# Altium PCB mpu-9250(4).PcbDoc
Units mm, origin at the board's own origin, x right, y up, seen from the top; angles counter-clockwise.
Board outline 66.04 x 76.71 mm, 2 copper layers (Top Layer, Bottom Layer); 14 components, 28 nets, 182 pads, 22 vias.
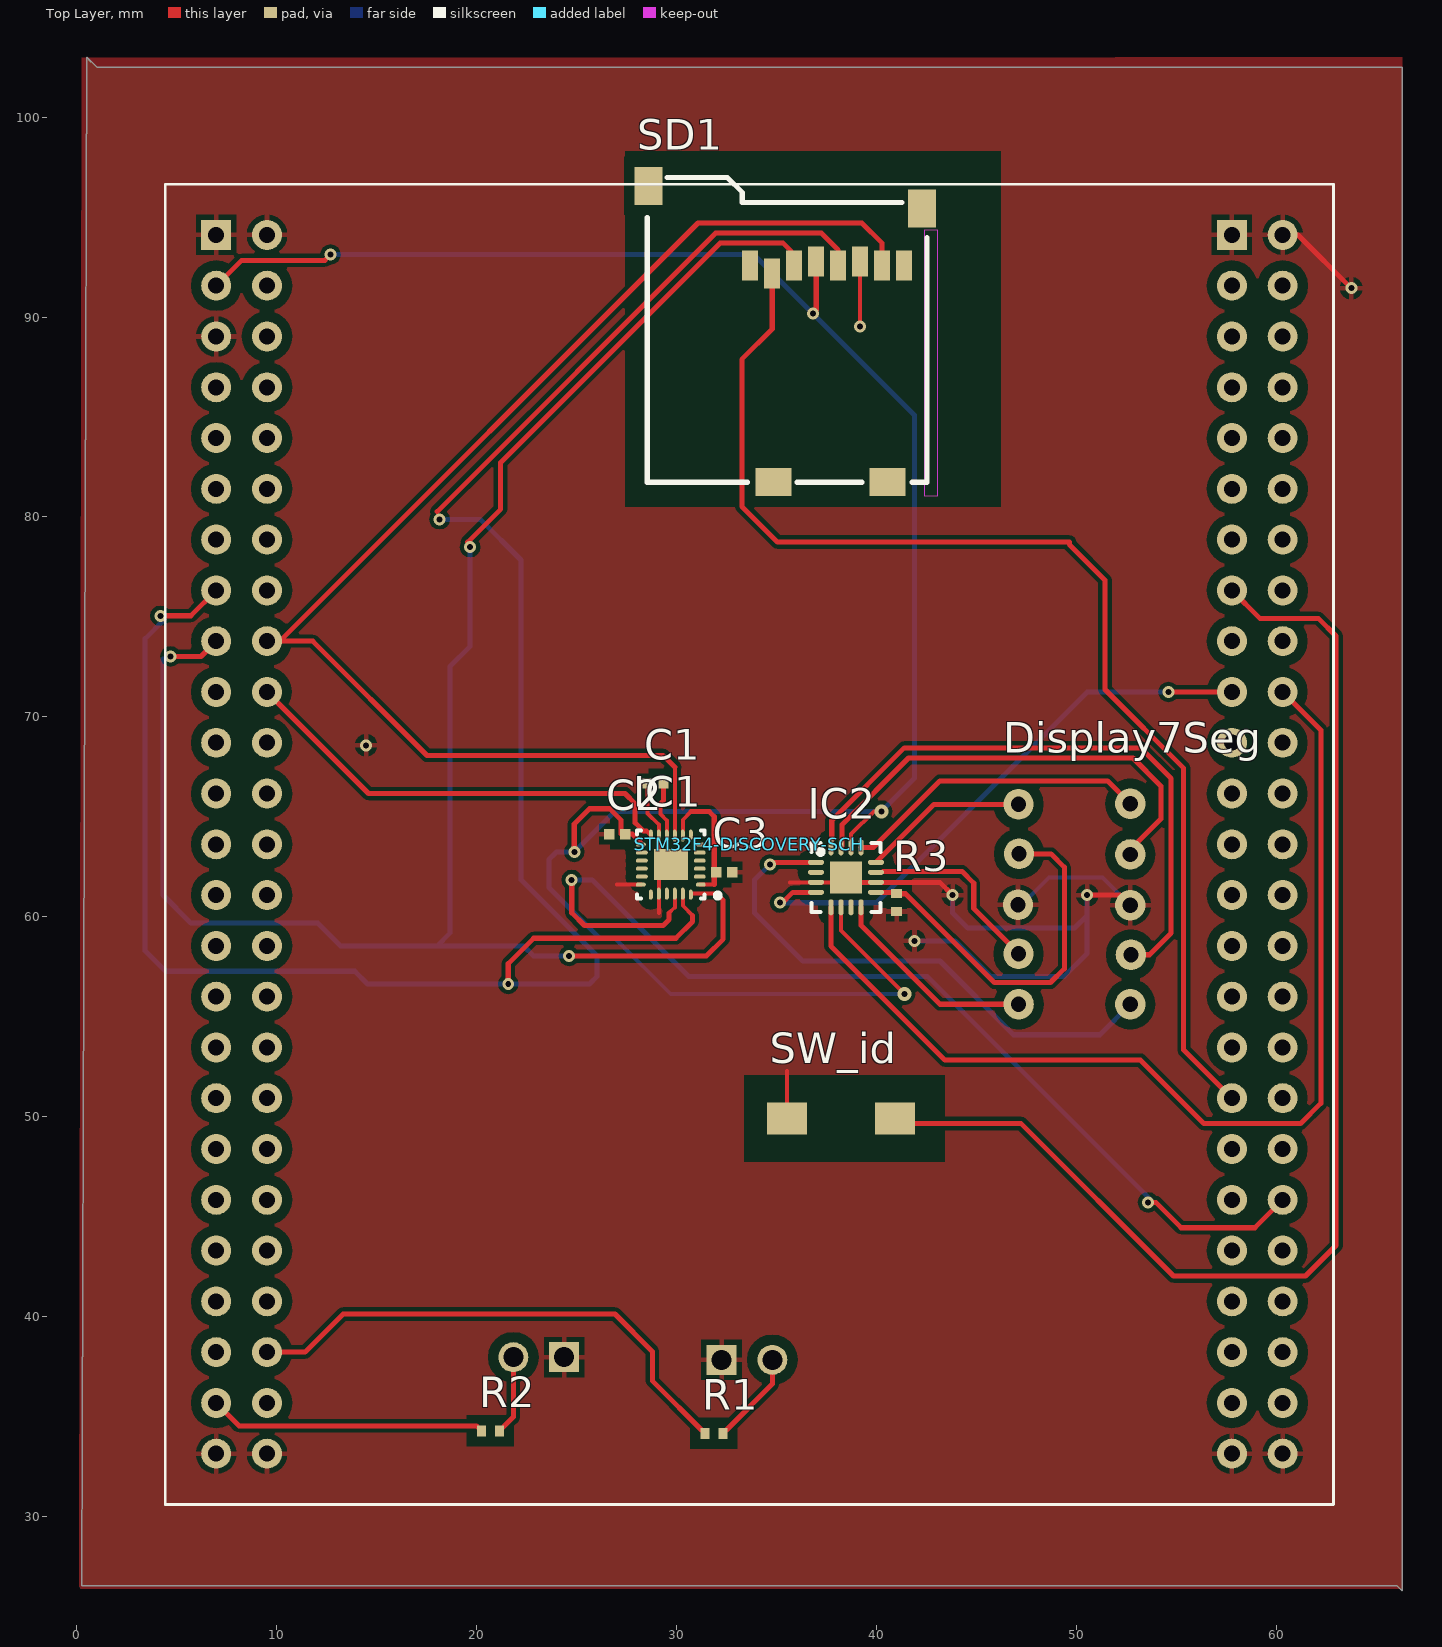
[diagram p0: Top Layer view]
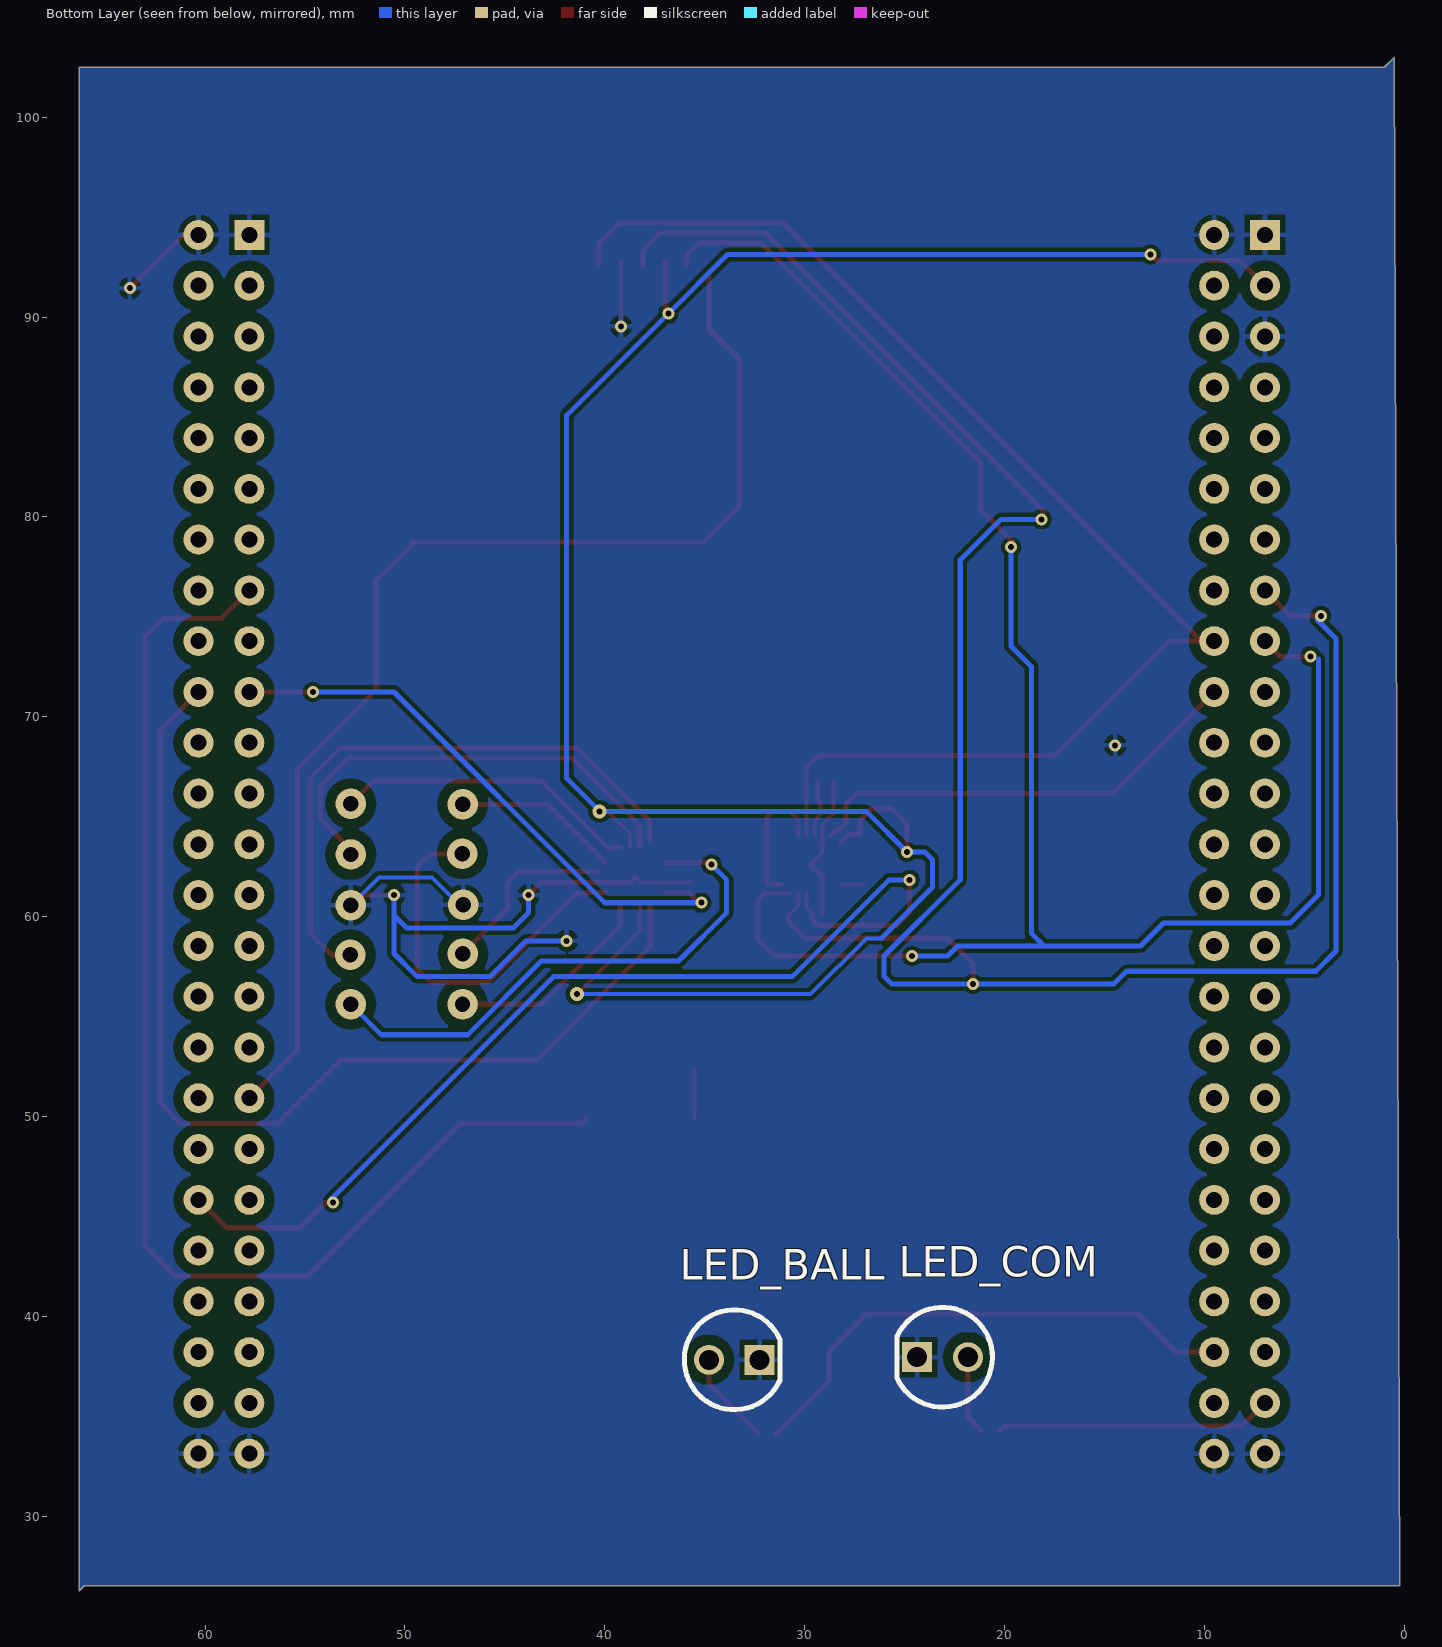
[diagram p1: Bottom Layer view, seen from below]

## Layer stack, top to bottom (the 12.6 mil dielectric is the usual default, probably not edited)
Top Solder: solder mask 0.0102, Solder Resist, Dk 3.5
Top Layer: signal copper 0.0356
Dielectric 1: dielectric 0.32, FR-4, Dk 4.8
Bottom Layer: signal copper 0.0356
Bottom Solder: solder mask 0.0102, Solder Resist, Dk 3.5

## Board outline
0.508,102.997 1.016,102.489 66.294,102.489 66.294,26.289 66.04,26.543 0.254,26.543

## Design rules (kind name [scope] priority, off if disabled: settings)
Clearance [All] p1: gap=0.2 ignorepadtopadclearanceinfootprint=FALSE except(0.5: SMDPad-Poly THPad-Poly)
PolygonConnect [All] p1: connectstyle=Relief reliefconductorwidth=0.254 reliefentries=4 polygonreliefangle="90 Angle" airgapwidth=0.254
RoutingVias [All] p1: holewidth=0.3 width=0.7 viastyle="Through Hole" minholewidth=0.3 minwidth=0.7 maxholewidth=3 maxwidth=3
SolderMaskExpansion [All] p1: expansion=0.102
Width [All] p1: maxlimit=2 minlimit=0.2 preferedwidth=0.3
30 further rules are at their usual default settings.

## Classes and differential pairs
component class mpu-9250: C1 C2 C3 Display7Seg IC1 IC2 LED_BALL LED_COM R1 R2 R3 SD1 SW_id

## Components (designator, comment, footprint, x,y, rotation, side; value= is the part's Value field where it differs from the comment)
C1 "100nF" 0402-CAP 28.956,66.675 r180 top value=100n
C2 "100nF" 0402-CAP 27.051,64.135 r180 top value=100n
C3 "1uF" 0402-CAP 32.385,62.23 r0 top value=1u
Display7Seg "HDSP-F513" "New footprint 1"#1 49.911,60.452 r180 top
IC1 "MPU-9250" MPU-9250 29.718,62.611 r180 top
IC2 "STMPE811QTR" QFN16_N 38.481,61.976 r0 top
LED_BALL "LED" LED-5MM-PCB 33.528,37.846 r180 bottom
LED_COM "LED" LED-5MM-PCB 23.114,37.973 r0 bottom
R1 "330R" 0402-RES-HD 31.877,34.163 r0 top value=330
R2 "330R" 0402-RES-HD 20.701,34.29 r0 top value=330
R3 "10K" 0402-RES-HD 41.021,60.706 r270 top
SD1 "2908-05WB-MG" "New footprint 1"#2 35.433,89.154 r0 top
STM32F4-DISCOVERY-SCH "STM32F4-DISCOVERY-SCH" STM32F4-DISCOVERY-PCB 33.655,63.627 r0 top
SW_id "SWITCH TACTILE 6 x 3.5 x 4.3 mm" PCBComponent 38.227,49.911 r180 top

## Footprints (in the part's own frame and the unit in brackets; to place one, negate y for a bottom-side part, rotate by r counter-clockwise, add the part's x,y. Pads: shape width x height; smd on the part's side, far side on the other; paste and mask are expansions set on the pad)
0402-CAP [mm] "Chip Capacitor, Body 1.0x0.5mm, Height 0.6mm, IPC Medium Density"
  rect 0.52x0.52 smd: 1(-0.4,0) 2(0.4,0)
  body extent -0.55,-0.3 0.55,0.3, height 0.33
0402-RES-HD [mm] "Chip Resistor, Body 1.0x0.5mm, IPC High Density"
  rect 0.45x0.55 smd: 1(-0.45,0) 2(0.45,0)
  body extent -0.52,-0.27 0.53,0.28, height 0.4
LED-5MM-PCB [mm]
  rect 1.5x1.5 hole 1: 1(1.27,0)
  round 1.5 hole 1: 2(-1.27,0)
  silkscreen extent -2.5,-2.5 2.28,2.5, body extent -2.98,-3.01 2.44,3.01, height 8.59
MPU-9250 [mm] "IMU ACCEL/GYRO/MAG I2C/SPI 24QFN"
  oval 0.5x0.2 smd: 1(-1.5,1) 6(-1.5,-1) 13(1.5,-1) 18(1.5,1)
  oval 0.6x0.2 smd: 2(-1.45,0.6) 3(-1.45,0.2) 4(-1.45,-0.2) 5(-1.45,-0.6) 14(1.45,-0.6) 15(1.45,-0.2) 16(1.45,0.2) 17(1.45,0.6)
  oval 0.2x0.5 smd: 7(-1,-1.5) 12(1,-1.5) 19(1,1.5) 24(-1,1.5)
  oval 0.2x0.6 smd: 8(-0.6,-1.45) 9(-0.2,-1.45) 10(0.2,-1.45) 11(0.6,-1.45) 20(0.6,1.45) 21(0.2,1.45) 22(-0.2,1.45) 23(-0.6,1.45)
  rect 1.7x1.54 smd: 25(0,0)
  silkscreen extent -2.48,-1.7 1.7,1.7, body extent -1.55,-1.55 1.55,1.55, height 1.05
"New footprint 1"#1 [mil]
  round 60 hole 30: 1(-110,190) 2(-111.22,92.52) 3(-110,-5) 4(-110,-105) 5(-110,-205) 6(110,190) 7(110.24,90.55) 8(111.22,-5.91) 9(109.25,-106.3) 10(110.24,-203.74)
  body extent -149,-255 150,245, height 283
"New footprint 1"#2 [mil]
  rect 31.5x59.06 smd: 1(-68.5,135.04) 2(-25.2,119.29) 3(18.11,135.04) 4(61.42,142.91) 5(104.72,135.04) 6(148.03,142.91) 7(191.34,135.04) 8(234.65,135.04)
  rect 55.12x74.8 smd: M1(269.29,246.85) M2(-269.29,291.73)
  rect 70.87x55.12 smd: M3(201.97,-291.73) M4(-22.44,-291.73)
  silkscreen extent -271,-292 280,308, body extent -269,-292 282,309, height 75
PCBComponent [mm]
  rect 2x1.6 smd: 1(-2.7,0) 2(2.7,0)
  body extent -3.65,-1.75 3.65,1.75, height 5
QFN16_N [mm] "QFN, 16-Leads, Body 3x3mm, Pitch 0.5mm, Thermal Pad 1.6x1.6mm, IPC Medium Density"
  oval 0.8x0.25 smd: 1(-1.5,0.75) 2(-1.5,0.25) 3(-1.5,-0.25) 4(-1.5,-0.75) 9(1.5,-0.75) 10(1.5,-0.25) 11(1.5,0.25) 12(1.5,0.75)
  oval 0.25x0.8 smd: 5(-0.75,-1.5) 6(-0.25,-1.5) 7(0.25,-1.5) 8(0.75,-1.5) 13(0.75,1.5) 14(0.25,1.5) 15(-0.25,1.5) 16(-0.75,1.5)
  rect 1.6x1.6 smd: TH(0,0)
  silkscreen extent -1.73,-1.73 1.73,1.73, body extent -1.58,-1.58 1.58,1.58, height 1
STM32F4-DISCOVERY-PCB [mm]
  rect 1.5x1.5 hole 0.8: P1_1(-26.67,30.48) P2_1(24.13,30.48)
  round 1.5 hole 0.8: P1_2(-24.13,30.48) P1_3(-26.67,27.94) P1_4(-24.13,27.94) P1_5(-26.67,25.4) P1_6(-24.13,25.4) P1_7(-26.67,22.86) P1_8(-24.13,22.86) P1_9(-26.67,20.32) P1_10(-24.13,20.32) P1_11(-26.67,17.78) P1_12(-24.13,17.78) P1_13(-26.67,15.24) P1_14(-24.13,15.24) P1_15(-26.67,12.7) P1_16(-24.13,12.7) P1_17(-26.67,10.16) P1_18(-24.13,10.16) P1_19(-26.67,7.62) P1_20(-24.13,7.62) P1_21(-26.67,5.08) P1_22(-24.13,5.08) P1_23(-26.67,2.54) P1_24(-24.13,2.54) P1_25(-26.67,0) P1_26(-24.13,0) P1_27(-26.67,-2.54) P1_28(-24.13,-2.54) P1_29(-26.67,-5.08) P1_30(-24.13,-5.08) P1_31(-26.67,-7.62) P1_32(-24.13,-7.62) P1_33(-26.67,-10.16) P1_34(-24.13,-10.16) P1_35(-26.67,-12.7) P1_36(-24.13,-12.7) P1_37(-26.67,-15.24) P1_38(-24.13,-15.24) P1_39(-26.67,-17.78) P1_40(-24.13,-17.78) P1_41(-26.67,-20.32) P1_42(-24.13,-20.32) P1_43(-26.67,-22.86) P1_44(-24.13,-22.86) P1_45(-26.67,-25.4) P1_46(-24.13,-25.4) P1_47(-26.67,-27.94) P1_48(-24.13,-27.94) P1_49(-26.67,-30.48) P1_50(-24.13,-30.48) P2_2(26.67,30.48) P2_3(24.13,27.94) P2_4(26.67,27.94) P2_5(24.13,25.4) P2_6(26.67,25.4) P2_7(24.13,22.86) P2_8(26.67,22.86) P2_9(24.13,20.32) P2_10(26.67,20.32) P2_11(24.13,17.78) P2_12(26.67,17.78) P2_13(24.13,15.24) P2_14(26.67,15.24) P2_15(24.13,12.7) P2_16(26.67,12.7) P2_17(24.13,10.16) P2_18(26.67,10.16) P2_19(24.13,7.62) P2_20(26.67,7.62) P2_21(24.13,5.08) P2_22(26.67,5.08) P2_23(24.13,2.54) P2_24(26.67,2.54) P2_25(24.13,0) P2_26(26.67,0) P2_27(24.13,-2.54) P2_28(26.67,-2.54) P2_29(24.13,-5.08) P2_30(26.67,-5.08) P2_31(24.13,-7.62) P2_32(26.67,-7.62) P2_33(24.13,-10.16) P2_34(26.67,-10.16) P2_35(24.13,-12.7) P2_36(26.67,-12.7) P2_37(24.13,-15.24) P2_38(26.67,-15.24) P2_39(24.13,-17.78) P2_40(26.67,-17.78) P2_41(24.13,-20.32) P2_42(26.67,-20.32) P2_43(24.13,-22.86) P2_44(26.67,-22.86) P2_45(24.13,-25.4) P2_46(26.67,-25.4) P2_47(24.13,-27.94) P2_48(26.67,-27.94) P2_49(24.13,-30.48) P2_50(26.67,-30.48)
  silkscreen extent -29.21,-33.02 29.21,33.02, body extent -32.77,-36.96 32.73,65.61, height 21.7

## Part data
C1 C2: library part CC0402-100nF-A.12, "CAP CER 0.1UF 10V 20% X5R 0402", Part No=VJ0402V104ZXQPBC
C3: library part CC0402-1uF-5, "CAP CER 1UF 6.3V 10% X5R 0402", Part No=JMK105BJ105KV-F
Display7Seg: library part HDSP-F513-01.A.1, "7 segments display"
IC1: library part MPU-9250-2, "IMU ACCEL/GYRO/MAG I2C/SPI 24QFN"
IC2: library part STMPE811QTR-6, "IC TSC I/O EXPAND 8B 16QFN"
LED_BALL LED_COM: library part LED-5MM-3, "LED 5MM PTH"
R1 R2: library part R0402-330R-7, "RES 330 OHM 1/10W 1% 0402 SMD", Part No=ERJ-2RKF3300X
R3: library part R0402-10K-11, "RES 10K OHM 1/10W 1% 0402 SMD", Part No=ERJ-2RKF1002X
SD1: library part 2908-05WB-MG-01.A.1, "CONN MICRO SD CARD PUSH-PUSH R/A"
SW_id: library part 95C04A3GWRT.-1, "GRAYHILL TACT,GW,6X3.5,1800T&R,LF Eight, 160g Operating Force, Gull Wing, RoHS Compliant", Part No=95C04A3GWRT

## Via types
v1: diameter 0.6, hole 0.3, Top Layer to Bottom Layer, 20 vias
v2: diameter 0.7, hole 0.3, Top Layer to Bottom Layer, 2 vias

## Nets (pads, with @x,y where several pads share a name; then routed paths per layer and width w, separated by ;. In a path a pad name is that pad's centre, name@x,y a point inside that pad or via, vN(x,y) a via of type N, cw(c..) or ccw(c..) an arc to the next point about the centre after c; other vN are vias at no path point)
a: Display7Seg.6 IC2.8 | length 10.4
  Top Layer w0.254: IC2.8 39.231,59.575 43.18,55.626 Display7Seg.6
b: Display7Seg.7 IC2.11 | length 9.2
  Top Layer w0.254: IC2.11@40.34,62.274 44.279,62.274 44.871,61.682 44.871,60.412 47.111,58.172 Display7Seg.7
Blue_led: R2.1 STM32F4-DISCOVERY-SCH.P1_47 | length 13.8
  Top Layer w0.254: STM32F4-DISCOVERY-SCH.P1_47 8.128,34.544 19.997,34.544 R2.1
c: Display7Seg.10 IC2.12 | length 8.3
  Top Layer w0.254: IC2.12 42.882,65.627 Display7Seg.10
d: Display7Seg.5 IC2.13 | length 15.3
  Top Layer w0.254: IC2.13 39.854,63.476 43.18,66.802 51.562,66.802 Display7Seg.5
DP: Display7Seg.9 IC2.9 R3.1 | length 19.2
  Top Layer w0.254: IC2.9 40.893,61.226 R3.1@41.021,61.098 ; R3.1 41.46,61.156 45.901,56.715 48.714,56.715 49.403,57.404 49.403,62.484 48.735,63.152 Display7Seg.9
e: Display7Seg.4 IC2.15 | length 23.1
  Top Layer w0.254: IC2.15 38.279,63.524 38.279,64.612 41.612,67.945 52.832,67.945 54.229,66.548 54.229,64.897 52.705,63.373 Display7Seg.4
f: Display7Seg.2 IC2.16 | length 30.3
  Top Layer w0.254: IC2.16@37.771,63.835 37.771,64.822 41.402,68.453 53.213,68.453 54.737,66.929 54.737,59.182 53.657,58.102 Display7Seg.2
g: Display7Seg.1 IC2.1 | length 26.9
  Top Layer w0.254: v1@34.81,62.726 IC2.1
  Bottom Layer w0.254: v1(34.671,62.611) 33.909,61.849 33.909,60.198 36.322,57.785 43.18,57.785 46.863,54.102 51.181,54.102 Display7Seg.1
GND: C1.2 C2.2 C3.2 Display7Seg.3 Display7Seg.8 IC1.11 IC1.18 IC1.20 IC1.25 IC2.3 IC2.10 IC2.TH LED_BALL.1 LED_COM.1 R3.2 SD1.6 STM32F4-DISCOVERY-SCH.P1_1 STM32F4-DISCOVERY-SCH.P1_2 STM32F4-DISCOVERY-SCH.P1_5 STM32F4-DISCOVERY-SCH.P1_49 STM32F4-DISCOVERY-SCH.P1_50 STM32F4-DISCOVERY-SCH.P2_1 STM32F4-DISCOVERY-SCH.P2_2 STM32F4-DISCOVERY-SCH.P2_49 STM32F4-DISCOVERY-SCH.P2_50 SW_id.2 | length 57.4
  Top Layer w0.2: 27.035,61.611 IC1.18 ; C1.2 28.556,65.17 29.118,64.608 IC1.11 29.118,63.211 IC1.25 ; 29.118,60.201 IC1.20 IC1.25@29.118,62.011 ; SW_id.2 35.527,52.291 ; 35.683,61.726 IC2.3 38.231,61.726 IC2.TH ; v1@39.193,89.358 SD1.6
  Top Layer w0.254: IC2.TH 38.731,61.726 IC2.10 43.176,61.726 v1(43.815,61.087) ; v1(50.546,61.087) 52.197,61.087 Display7Seg.3 ; STM32F4-DISCOVERY-SCH.P2_2 61.087,94.107 v1(63.754,91.44)
  Top Layer w0.3: IC1.25@29.118,62.011 IC1.25
  Bottom Layer w0.2: Display7Seg.8 47.267,60.602 48.641,61.976 51.308,61.976 Display7Seg.3
  Bottom Layer w0.254: v1(41.91,58.801) 43.942,58.801 45.72,57.023 49.403,57.023 50.546,58.166 50.546,60.071 ; v1(43.815,61.087) 43.815,60.198 44.577,59.436 49.911,59.436 50.546,60.071 ; v1(50.546,61.087) 50.546,60.071
  other v1: 14.478,68.58 39.193,89.535
ID_button: STM32F4-DISCOVERY-SCH.P2_15 SW_id.1 | length 62.6
  Top Layer w0.254: SW_id.1 41.181,49.657 47.244,49.657 54.864,42.037 61.468,42.037 62.992,43.561 62.992,74.041 62.103,74.93 59.182,74.93 STM32F4-DISCOVERY-SCH.P2_15
INT_MPU: IC1.12 STM32F4-DISCOVERY-SCH.P1_20 | length 22.7
  Top Layer w0.2: 28.496,64.283 IC1.12@28.718,64.061
  Top Layer w0.254: STM32F4-DISCOVERY-SCH.P1_20 14.605,66.167 27.432,66.167 27.94,65.659 27.94,64.707 28.364,64.283 28.496,64.283
MISO: IC1.9 SD1.7 STM32F4-DISCOVERY-SCH.P1_18 | length 66.8
  Top Layer w0.2: IC1.9 29.918,67.491
  Top Layer w0.254: STM32F4-DISCOVERY-SCH.P1_18 STM32F4-DISCOVERY-SCH.P1_18@10.16,73.787 ; 29.918,67.491 29.337,68.072 17.526,68.072 11.811,73.787 STM32F4-DISCOVERY-SCH.P1_18@10.16,73.787 ; SD1.7 40.293,93.692 39.277,94.708 31.081,94.708 STM32F4-DISCOVERY-SCH.P1_18@10.16,73.787
MOSI: IC1.24 SD1.3 STM32F4-DISCOVERY-SCH.P1_17 | length 93.1
  Top Layer w0.2: IC1.24@30.718,61.161 32.011,61.161
  Top Layer w0.254: v1(4.699,73.025) 6.223,73.025 STM32F4-DISCOVERY-SCH.P1_17 ; v1@19.558,78.74 21.209,80.391 21.209,82.721 32.18,93.692 35.34,93.692 35.893,93.139 SD1.3 ; v1(24.638,58.039) 31.496,58.039 32.339,58.882 32.339,60.833 32.011,61.161
  Bottom Layer w0.254: 4.318,72.898 4.318,61.087 5.715,59.69 12.065,59.69 13.208,58.547 18.034,58.547 ; v1(19.685,78.486) 19.685,73.533 18.669,72.517 18.669,59.182 18.034,58.547 ; v1(24.638,58.039) 22.86,58.039 22.352,58.547 18.034,58.547
MPU_CS: IC1.22 STM32F4-DISCOVERY-SCH.P2_40 | length 51.7
  Top Layer w0.2: 29.637,60.198 29.918,60.479 IC1.22
  Top Layer w0.254: v1(24.765,61.849) 24.765,60.198 25.4,59.563 29.337,59.563 29.637,59.863 29.637,60.198 ; v1(53.594,45.72) 53.975,45.72 55.245,44.45 58.928,44.45 STM32F4-DISCOVERY-SCH.P2_40
  Bottom Layer w0.254: v1(24.765,61.849) 25.781,61.849 30.607,57.023 42.545,57.023 v1@53.721,45.847
NetC1_1: C1.1 IC1.10 | length 2.8
  Top Layer w0.2: 29.21,65.659 29.21,65.132 29.518,64.824 IC1.10
  Top Layer w0.254: 29.21,65.659 29.356,65.805 C1.1
NetC3_1: C3.1 IC1.1 IC1.8 | length 6.8
  Top Layer w0.2: IC1.8 30.318,64.843 30.734,65.259 ; IC1.1@31.168,61.611 31.893,61.611
  Top Layer w0.254: 30.734,65.259 31.642,65.259 31.893,65.008 31.893,61.611
NetLED_BALL_2: LED_BALL.2 R1.2 | length 4.7
  Top Layer w0.254: R1.2 34.798,36.634 LED_BALL.2
NetLED_COM_2: LED_COM.2 R2.2 | length 4
  Top Layer w0.254: R2.2 21.844,34.983 LED_COM.2
NRF_CE: STM32F4-DISCOVERY-SCH.P1_13
NRF_CS#: STM32F4-DISCOVERY-SCH.P1_16
NRF_IRQ: STM32F4-DISCOVERY-SCH.P1_19
Red_led: R1.1 STM32F4-DISCOVERY-SCH.P1_46 | length 26
  Top Layer w0.254: STM32F4-DISCOVERY-SCH.P1_46 11.43,38.227 13.335,40.132 26.924,40.132 28.795,38.261 28.795,36.795 R1.1
SCK: IC1.23 SD1.5 STM32F4-DISCOVERY-SCH.P1_15 | length 111
  Top Layer w0.2: IC1.23 30.318,60.568 30.815,60.071
  Top Layer w0.254: v1(4.191,75.057) 5.715,75.057 STM32F4-DISCOVERY-SCH.P1_15 STM32F4-DISCOVERY-SCH.P1_15@6.985,76.073 ; 18.034,80.264 31.97,94.2 37.245,94.2 38.093,93.352 SD1.5 ; v1(21.59,56.642) 21.59,57.658 22.86,58.928 29.972,58.928 30.815,59.771 30.815,60.071
  Bottom Layer w0.254: v1@4.381,74.867 3.429,73.914 3.429,58.293 4.445,57.277 13.913,57.277 14.548,56.642 v1(21.59,56.642) 25.654,56.642 26.035,57.023 26.035,58.039 22.225,61.849 22.225,77.851 20.193,79.883 v1(18.161,79.883)
SCL: IC2.4 STM32F4-DISCOVERY-SCH.P2_19 | length 29
  Top Layer w0.254: v1@35.242,60.642 35.826,61.226 IC2.4 ; v1(54.61,71.247) STM32F4-DISCOVERY-SCH.P2_19
  Bottom Layer w0.254: v1(35.179,60.706) 40.005,60.706 50.546,71.247 v1(54.61,71.247)
SDA: IC2.5 STM32F4-DISCOVERY-SCH.P2_20 | length 51.9
  Top Layer w0.254: IC2.5 37.731,58.535 43.434,52.832 53.213,52.832 56.388,49.657 61.214,49.657 62.23,50.673 62.23,69.342 STM32F4-DISCOVERY-SCH.P2_20
uSD_CS: SD1.2 STM32F4-DISCOVERY-SCH.P2_35 | length 60.6
  Top Layer w0.254: SD1.2 34.793,89.403 33.274,87.884 33.274,80.518 35.052,78.74 49.657,78.74 49.657,78.613 51.435,76.835 51.435,71.374 55.372,67.437 55.372,53.34 STM32F4-DISCOVERY-SCH.P2_35
VDD: C2.1 IC1.13 IC2.6 IC2.14 SD1.4 STM32F4-DISCOVERY-SCH.P1_3 | length 114.9
  Top Layer w0.2: IC2.6 38.231,59.305 v2(41.402,56.134) ; IC2.14 38.731,64.131 39.878,65.278
  Top Layer w0.254: STM32F4-DISCOVERY-SCH.P1_3 8.255,92.837 12.411,92.837 v1(12.7,93.126) ; v1(24.892,63.246) 24.892,64.643 25.654,65.405 26.67,65.405 27.238,64.837 27.238,64.135 C2.1 27.794,64.135 28.207,63.722 ; v1@36.993,90.333 SD1.4
  Bottom Layer w0.2: 26.162,58.928 26.924,58.928 29.718,56.134 v2(41.402,56.134)
  Bottom Layer w0.254: v1(12.7,93.126) 33.874,93.126 v1(36.83,90.17) 41.91,85.09 41.91,66.929 v2(40.259,65.278) 26.924,65.278 v1(24.892,63.246) 24.003,63.246 23.622,62.865 23.622,61.468 26.162,58.928
pads on no net: IC1.2 IC1.3 IC1.4 IC1.5 IC1.6 IC1.7 IC1.14 IC1.15 IC1.16 IC1.17 IC1.19 IC1.21 IC2.2 IC2.7 SD1.1 SD1.8 SD1.M1 SD1.M2 SD1.M3 SD1.M4 STM32F4-DISCOVERY-SCH.P1_4 STM32F4-DISCOVERY-SCH.P1_6 STM32F4-DISCOVERY-SCH.P1_7 STM32F4-DISCOVERY-SCH.P1_8 STM32F4-DISCOVERY-SCH.P1_9 STM32F4-DISCOVERY-SCH.P1_10 STM32F4-DISCOVERY-SCH.P1_11 STM32F4-DISCOVERY-SCH.P1_12 STM32F4-DISCOVERY-SCH.P1_14 STM32F4-DISCOVERY-SCH.P1_21 STM32F4-DISCOVERY-SCH.P1_22 STM32F4-DISCOVERY-SCH.P1_23 STM32F4-DISCOVERY-SCH.P1_24 STM32F4-DISCOVERY-SCH.P1_25 STM32F4-DISCOVERY-SCH.P1_26 STM32F4-DISCOVERY-SCH.P1_27 STM32F4-DISCOVERY-SCH.P1_28 STM32F4-DISCOVERY-SCH.P1_29 STM32F4-DISCOVERY-SCH.P1_30 STM32F4-DISCOVERY-SCH.P1_31 STM32F4-DISCOVERY-SCH.P1_32 STM32F4-DISCOVERY-SCH.P1_33 STM32F4-DISCOVERY-SCH.P1_34 STM32F4-DISCOVERY-SCH.P1_35 STM32F4-DISCOVERY-SCH.P1_36 STM32F4-DISCOVERY-SCH.P1_37 STM32F4-DISCOVERY-SCH.P1_38 STM32F4-DISCOVERY-SCH.P1_39 STM32F4-DISCOVERY-SCH.P1_40 STM32F4-DISCOVERY-SCH.P1_41 STM32F4-DISCOVERY-SCH.P1_42 STM32F4-DISCOVERY-SCH.P1_43 STM32F4-DISCOVERY-SCH.P1_44 STM32F4-DISCOVERY-SCH.P1_45 STM32F4-DISCOVERY-SCH.P1_48 STM32F4-DISCOVERY-SCH.P2_3 STM32F4-DISCOVERY-SCH.P2_4 STM32F4-DISCOVERY-SCH.P2_5 STM32F4-DISCOVERY-SCH.P2_6 STM32F4-DISCOVERY-SCH.P2_7 STM32F4-DISCOVERY-SCH.P2_8 STM32F4-DISCOVERY-SCH.P2_9 STM32F4-DISCOVERY-SCH.P2_10 STM32F4-DISCOVERY-SCH.P2_11 STM32F4-DISCOVERY-SCH.P2_12 STM32F4-DISCOVERY-SCH.P2_13 STM32F4-DISCOVERY-SCH.P2_14 STM32F4-DISCOVERY-SCH.P2_16 STM32F4-DISCOVERY-SCH.P2_17 STM32F4-DISCOVERY-SCH.P2_18 STM32F4-DISCOVERY-SCH.P2_21 STM32F4-DISCOVERY-SCH.P2_22 STM32F4-DISCOVERY-SCH.P2_23 STM32F4-DISCOVERY-SCH.P2_24 STM32F4-DISCOVERY-SCH.P2_25 STM32F4-DISCOVERY-SCH.P2_26 STM32F4-DISCOVERY-SCH.P2_27 STM32F4-DISCOVERY-SCH.P2_28 STM32F4-DISCOVERY-SCH.P2_29 STM32F4-DISCOVERY-SCH.P2_30 STM32F4-DISCOVERY-SCH.P2_31 STM32F4-DISCOVERY-SCH.P2_32 STM32F4-DISCOVERY-SCH.P2_33 STM32F4-DISCOVERY-SCH.P2_34 STM32F4-DISCOVERY-SCH.P2_36 STM32F4-DISCOVERY-SCH.P2_37 STM32F4-DISCOVERY-SCH.P2_38 STM32F4-DISCOVERY-SCH.P2_39 STM32F4-DISCOVERY-SCH.P2_41 STM32F4-DISCOVERY-SCH.P2_42 STM32F4-DISCOVERY-SCH.P2_43 STM32F4-DISCOVERY-SCH.P2_44 STM32F4-DISCOVERY-SCH.P2_45 STM32F4-DISCOVERY-SCH.P2_46 STM32F4-DISCOVERY-SCH.P2_47 STM32F4-DISCOVERY-SCH.P2_48

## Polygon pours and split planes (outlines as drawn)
GND on Top Layer "gnd top" (solid, pour order 2): 15.113,26.397 51.816,26.397 66.294,26.397 66.294,102.997 51.943,102.997 51.943,102.978 15.113,102.978 0.254,102.978 0.129,26.397
GND on Bottom Layer "Top Layer-No Net" (solid, pour order 4): 0.508,102.997 1.016,102.489 66.294,102.489 66.294,26.289 66.04,26.543 0.254,26.543

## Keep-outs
Top Layer:
  region: 42.418,94.361 43.053,94.361 43.053,81.026 42.418,81.026

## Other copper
Top Layer:
  pour cut-out: 33.401,52.07 33.401,47.752 43.434,47.752 43.434,52.07
  pour cut-out: 47.244,100.33
  pour cut-out: 27.432,98.298 46.228,98.298 46.228,80.518 27.432,80.518

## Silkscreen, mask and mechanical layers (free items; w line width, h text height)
Mechanical 1:
  the board outline again, w0.5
